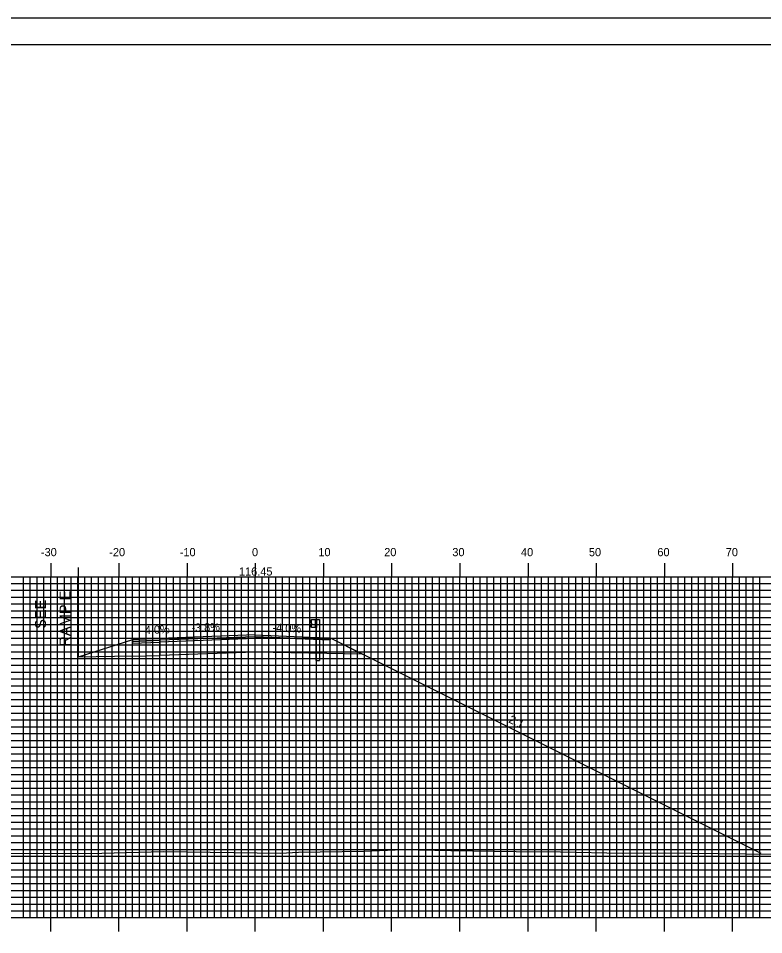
# Model space of a CAD drawing. Extents: x -302 to 42, y -1658 to -1438.
# Drawn here: x -170.6 to -61.3, y -1572.1 to -1437.7 of the extents above; entities that cross this region are included whole.
import ezdxf

# ---------------------------------------------------------------- set-up
doc = ezdxf.new("R2010")
doc.units = 0
for name, color, linetype in [('ANNOTATION', 7, 'Continuous'), ('BORDER', 7, 'Continuous'), ('D_Guardrail_Beam_Rt', 7, 'Continuous'), ('D_Roadway_Centerline_Text', 7, 'Continuous'), ('D_Roadway_Edge_Shoulder', 7, 'Continuous'), ('D_Roadway_Pavement', 7, 'Continuous'), ('D_Roadway_SlopeLines', 7, 'Continuous'), ('D_Roadway_SubGrade', 7, 'Continuous'), ('H_V ANNOTATION', 7, 'Continuous'), ('MAJOR', 7, 'Continuous'), ('MINOR', 7, 'Continuous'), ('PLOT BOUNDARY', 7, 'Continuous'), ('S_Roadway_Centerline', 7, 'Continuous')]:
    doc.layers.add(name, color=color, linetype=linetype)

msp = doc.modelspace()

# ---------------------------------------------------------------- linework, layer by layer
at = {"layer": 'BORDER'}
msp.add_lwpolyline([(-285.49, -1651.6), (34.51, -1651.6), (34.51, -1441.6), (-285.49, -1441.6)], close=True, dxfattribs=at)
at = {"layer": 'D_Guardrail_Beam_Rt'}
for p, q in [((-127.71, -1525.99), (-127.85, -1526.09)), ((-127.85, -1526.24), (-127.66, -1526.37)), ((-127.62, -1525.97), (-127.7, -1525.99)), ((-127.63, -1526.44), (-127.63, -1526.51)), ((-127.62, -1525.89), (-126.93, -1525.89)), ((-127.62, -1527.06), (-127.62, -1525.89)), ((-127.1, -1525.89), (-127.1, -1527.06)), ((-127, -1525.89), (-127, -1527.06)), ((-126.93, -1525.89), (-126.46, -1525.89)), ((-126.93, -1525.89), (-126.93, -1527.06)), ((-126.46, -1525.89), (-126.46, -1531.89)), ((-127.66, -1526.57), (-127.85, -1526.71)), ((-127.85, -1526.85), (-127.71, -1526.95)), ((-127.7, -1526.96), (-127.62, -1526.97)), ((-126.93, -1527.06), (-127.62, -1527.06)), ((-126.95, -1531.89), (-126.95, -1527.06)), ((-126.95, -1531.89), (-126.46, -1531.89))]:
    msp.add_line(p, q, dxfattribs=at)
for centre, major_axis, start_param, end_param in [((-127.8, -1526.17), (-0.0877, 0), 5.323254, 7.243116), ((-127.69, -1526.03), (-0.0417, 0), 4.907132, 5.323254), ((-127.7, -1526.44), (0.0789, 0), 0, 0.959931), ((-127.8, -1526.78), (-0.0877, 0), 5.323254, 7.243116), ((-127.69, -1526.92), (-0.0417, 0), 0.959931, 1.376053), ((-127.7, -1526.51), (0.0789, 0), 5.323254, 6.283185)]:
    msp.add_ellipse(centre, major_axis=major_axis, ratio=0.995501, start_param=start_param, end_param=end_param, dxfattribs=at)
at = {"layer": 'D_Roadway_Edge_Shoulder'}
for points in [[(-149.89, -1528.68), (-153.89, -1528.84), (-153.89, -1529.09), (-149.89, -1528.93)], [(-135.89, -1528.15), (-127.89, -1528.47), (-127.89, -1528.47), (-124.89, -1528.59), (-124.89, -1528.84), (-135.89, -1528.4)]]:
    msp.add_lwpolyline(points, close=True, dxfattribs=at)
at = {"layer": 'D_Roadway_Pavement'}
msp.add_lwpolyline([(-149.89, -1528.93), (-153.89, -1529.09), (-153.89, -1529.34), (-149.89, -1529.18)], close=True, dxfattribs=at)
msp.add_lwpolyline([(-135.89, -1528.4), (-135.89, -1528.65)], dxfattribs=at)
msp.add_lwpolyline([(-135.89, -1528.4), (-135.89, -1528.65)], dxfattribs=at)
at = {"layer": 'D_Roadway_SlopeLines'}
for p, q in [((-153.89, -1528.84), (-161.84, -1531.41)), ((-135.89, -1528.15), (-149.89, -1528.68)), ((-135.89, -1528.4), (-149.89, -1528.93)), ((-135.89, -1528.65), (-149.89, -1529.18)), ((-149.89, -1528.68), (-149.89, -1531.18)), ((-124.89, -1528.59), (-61.77, -1560.15)), ((-153.89, -1531.26), (-161.87, -1531.42)), ((-135.89, -1530.65), (-149.89, -1531.18))]:
    msp.add_line(p, q, dxfattribs=at)
at = {"layer": 'D_Roadway_SubGrade'}
for p, q in [((-161.84, -1518.27), (-161.84, -1531.41)), ((-153.89, -1531.26), (-149.89, -1531.18))]:
    msp.add_line(p, q, dxfattribs=at)
msp.add_lwpolyline([(-135.89, -1528.65), (-135.89, -1528.4), (-124.89, -1528.84), (-124.89, -1528.59), (-120.14, -1530.97), (-135.89, -1530.65)], close=True, dxfattribs=at)
at = {"layer": 'MAJOR'}
for p, q in [((-165.89, -1517.6), (-165.89, -1519.6)), ((-155.89, -1517.6), (-155.89, -1519.6)), ((-145.89, -1517.6), (-145.89, -1519.6)), ((-135.89, -1517.6), (-135.89, -1519.6)), ((-125.89, -1517.6), (-125.89, -1519.6)), ((-115.89, -1517.6), (-115.89, -1519.6)), ((-105.89, -1517.6), (-105.89, -1519.6)), ((-95.89, -1517.6), (-95.89, -1519.6)), ((-85.89, -1517.6), (-85.89, -1519.6)), ((-75.89, -1517.6), (-75.89, -1519.6)), ((-65.89, -1517.6), (-65.89, -1519.6)), ((-275.89, -1519.6), (4.11, -1519.6)), ((-275.89, -1519.6), (4.11, -1519.6)), ((-165.89, -1569.6), (-165.89, -1519.6)), ((-155.89, -1569.6), (-155.89, -1519.6)), ((-145.89, -1569.6), (-145.89, -1519.6)), ((-135.89, -1569.6), (-135.89, -1519.6)), ((-125.89, -1569.6), (-125.89, -1519.6)), ((-115.89, -1569.6), (-115.89, -1519.6)), ((-105.89, -1569.6), (-105.89, -1519.6)), ((-95.89, -1569.6), (-95.89, -1519.6)), ((-85.89, -1569.6), (-85.89, -1519.6)), ((-75.89, -1569.6), (-75.89, -1519.6)), ((-65.89, -1569.6), (-65.89, -1519.6)), ((-275.89, -1524.6), (4.11, -1524.6)), ((-275.89, -1529.6), (4.11, -1529.6)), ((-275.89, -1534.6), (4.11, -1534.6)), ((-275.89, -1539.6), (4.11, -1539.6)), ((-275.89, -1544.6), (4.11, -1544.6)), ((-275.89, -1549.6), (4.11, -1549.6)), ((-275.89, -1554.6), (4.11, -1554.6)), ((-275.89, -1559.6), (4.11, -1559.6)), ((-275.89, -1564.6), (4.11, -1564.6)), ((-275.89, -1569.6), (4.11, -1569.6)), ((-275.89, -1569.6), (4.11, -1569.6)), ((-165.89, -1571.61), (-165.89, -1569.6)), ((-155.89, -1571.61), (-155.89, -1569.6)), ((-145.89, -1571.61), (-145.89, -1569.6)), ((-135.89, -1571.61), (-135.89, -1569.6)), ((-125.89, -1571.61), (-125.89, -1569.6)), ((-115.89, -1571.61), (-115.89, -1569.6)), ((-105.89, -1571.61), (-105.89, -1569.6)), ((-95.89, -1571.61), (-95.89, -1569.6)), ((-85.89, -1571.61), (-85.89, -1569.6)), ((-75.89, -1571.61), (-75.89, -1569.6)), ((-65.89, -1571.61), (-65.89, -1569.6))]:
    msp.add_line(p, q, dxfattribs=at)
at = {"layer": 'MINOR'}
for p, q in [((-169.89, -1569.6), (-169.89, -1519.6)), ((-168.89, -1569.6), (-168.89, -1519.6)), ((-167.89, -1569.6), (-167.89, -1519.6)), ((-166.89, -1569.6), (-166.89, -1519.6)), ((-164.89, -1569.6), (-164.89, -1519.6)), ((-163.89, -1569.6), (-163.89, -1519.6)), ((-162.89, -1569.6), (-162.89, -1519.6)), ((-161.89, -1569.6), (-161.89, -1519.6)), ((-160.89, -1569.6), (-160.89, -1519.6)), ((-159.89, -1569.6), (-159.89, -1519.6)), ((-158.89, -1569.6), (-158.89, -1519.6)), ((-157.89, -1569.6), (-157.89, -1519.6)), ((-156.89, -1569.6), (-156.89, -1519.6)), ((-154.89, -1569.6), (-154.89, -1519.6)), ((-153.89, -1569.6), (-153.89, -1519.6)), ((-152.89, -1569.6), (-152.89, -1519.6)), ((-151.89, -1569.6), (-151.89, -1519.6)), ((-150.89, -1569.6), (-150.89, -1519.6)), ((-149.89, -1569.6), (-149.89, -1519.6)), ((-148.89, -1569.6), (-148.89, -1519.6)), ((-147.89, -1569.6), (-147.89, -1519.6)), ((-146.89, -1569.6), (-146.89, -1519.6)), ((-144.89, -1569.6), (-144.89, -1519.6)), ((-143.89, -1569.6), (-143.89, -1519.6)), ((-142.89, -1569.6), (-142.89, -1519.6)), ((-141.89, -1569.6), (-141.89, -1519.6)), ((-140.89, -1569.6), (-140.89, -1519.6)), ((-139.89, -1569.6), (-139.89, -1519.6)), ((-138.89, -1569.6), (-138.89, -1519.6)), ((-137.89, -1569.6), (-137.89, -1519.6)), ((-136.89, -1569.6), (-136.89, -1519.6)), ((-134.89, -1569.6), (-134.89, -1519.6)), ((-133.89, -1569.6), (-133.89, -1519.6)), ((-132.89, -1569.6), (-132.89, -1519.6)), ((-131.89, -1569.6), (-131.89, -1519.6)), ((-130.89, -1569.6), (-130.89, -1519.6)), ((-129.89, -1569.6), (-129.89, -1519.6)), ((-128.89, -1569.6), (-128.89, -1519.6)), ((-127.89, -1569.6), (-127.89, -1519.6)), ((-126.89, -1569.6), (-126.89, -1519.6)), ((-124.89, -1569.6), (-124.89, -1519.6)), ((-123.89, -1569.6), (-123.89, -1519.6)), ((-122.89, -1569.6), (-122.89, -1519.6)), ((-121.89, -1569.6), (-121.89, -1519.6)), ((-120.89, -1569.6), (-120.89, -1519.6)), ((-119.89, -1569.6), (-119.89, -1519.6)), ((-118.89, -1569.6), (-118.89, -1519.6)), ((-117.89, -1569.6), (-117.89, -1519.6)), ((-116.89, -1569.6), (-116.89, -1519.6)), ((-114.89, -1569.6), (-114.89, -1519.6)), ((-113.89, -1569.6), (-113.89, -1519.6)), ((-112.89, -1569.6), (-112.89, -1519.6)), ((-111.89, -1569.6), (-111.89, -1519.6)), ((-110.89, -1569.6), (-110.89, -1519.6)), ((-109.89, -1569.6), (-109.89, -1519.6)), ((-108.89, -1569.6), (-108.89, -1519.6)), ((-107.89, -1569.6), (-107.89, -1519.6)), ((-106.89, -1569.6), (-106.89, -1519.6)), ((-104.89, -1569.6), (-104.89, -1519.6)), ((-103.89, -1569.6), (-103.89, -1519.6)), ((-102.89, -1569.6), (-102.89, -1519.6)), ((-101.89, -1569.6), (-101.89, -1519.6)), ((-100.89, -1569.6), (-100.89, -1519.6)), ((-99.89, -1569.6), (-99.89, -1519.6)), ((-98.89, -1569.6), (-98.89, -1519.6)), ((-97.89, -1569.6), (-97.89, -1519.6)), ((-96.89, -1569.6), (-96.89, -1519.6)), ((-94.89, -1569.6), (-94.89, -1519.6)), ((-93.89, -1569.6), (-93.89, -1519.6)), ((-92.89, -1569.6), (-92.89, -1519.6)), ((-91.89, -1569.6), (-91.89, -1519.6)), ((-90.89, -1569.6), (-90.89, -1519.6)), ((-89.89, -1569.6), (-89.89, -1519.6)), ((-88.89, -1569.6), (-88.89, -1519.6)), ((-87.89, -1569.6), (-87.89, -1519.6)), ((-86.89, -1569.6), (-86.89, -1519.6)), ((-84.89, -1569.6), (-84.89, -1519.6)), ((-83.89, -1569.6), (-83.89, -1519.6)), ((-82.89, -1569.6), (-82.89, -1519.6)), ((-81.89, -1569.6), (-81.89, -1519.6)), ((-80.89, -1569.6), (-80.89, -1519.6)), ((-79.89, -1569.6), (-79.89, -1519.6)), ((-78.89, -1569.6), (-78.89, -1519.6)), ((-77.89, -1569.6), (-77.89, -1519.6)), ((-76.89, -1569.6), (-76.89, -1519.6)), ((-74.89, -1569.6), (-74.89, -1519.6)), ((-73.89, -1569.6), (-73.89, -1519.6)), ((-72.89, -1569.6), (-72.89, -1519.6)), ((-71.89, -1569.6), (-71.89, -1519.6)), ((-70.89, -1569.6), (-70.89, -1519.6)), ((-69.89, -1569.6), (-69.89, -1519.6)), ((-68.89, -1569.6), (-68.89, -1519.6)), ((-67.89, -1569.6), (-67.89, -1519.6)), ((-66.89, -1569.6), (-66.89, -1519.6)), ((-64.89, -1569.6), (-64.89, -1519.6)), ((-63.89, -1569.6), (-63.89, -1519.6)), ((-62.89, -1569.6), (-62.89, -1519.6)), ((-61.89, -1569.6), (-61.89, -1519.6)), ((-275.89, -1520.6), (4.11, -1520.6)), ((-275.89, -1521.6), (4.11, -1521.6)), ((-275.89, -1522.6), (4.11, -1522.6)), ((-275.89, -1523.6), (4.11, -1523.6)), ((-275.89, -1525.6), (4.11, -1525.6)), ((-275.89, -1526.6), (4.11, -1526.6)), ((-275.89, -1527.6), (4.11, -1527.6)), ((-275.89, -1528.6), (4.11, -1528.6)), ((-275.89, -1530.6), (4.11, -1530.6)), ((-275.89, -1531.6), (4.11, -1531.6)), ((-275.89, -1532.6), (4.11, -1532.6)), ((-275.89, -1533.6), (4.11, -1533.6)), ((-275.89, -1535.6), (4.11, -1535.6)), ((-275.89, -1536.6), (4.11, -1536.6)), ((-275.89, -1537.6), (4.11, -1537.6)), ((-275.89, -1538.6), (4.11, -1538.6)), ((-275.89, -1540.6), (4.11, -1540.6)), ((-275.89, -1541.6), (4.11, -1541.6)), ((-275.89, -1542.6), (4.11, -1542.6)), ((-275.89, -1543.6), (4.11, -1543.6)), ((-275.89, -1545.6), (4.11, -1545.6)), ((-275.89, -1546.6), (4.11, -1546.6)), ((-275.89, -1547.6), (4.11, -1547.6)), ((-275.89, -1548.6), (4.11, -1548.6)), ((-275.89, -1550.6), (4.11, -1550.6)), ((-275.89, -1551.6), (4.11, -1551.6)), ((-275.89, -1552.6), (4.11, -1552.6)), ((-275.89, -1553.6), (4.11, -1553.6)), ((-275.89, -1555.6), (4.11, -1555.6)), ((-275.89, -1556.6), (4.11, -1556.6)), ((-275.89, -1557.6), (4.11, -1557.6)), ((-275.89, -1558.6), (4.11, -1558.6)), ((-275.89, -1560.6), (4.11, -1560.6)), ((-275.89, -1561.6), (4.11, -1561.6)), ((-275.89, -1562.6), (4.11, -1562.6)), ((-275.89, -1563.6), (4.11, -1563.6)), ((-275.89, -1565.6), (4.11, -1565.6)), ((-275.89, -1566.6), (4.11, -1566.6)), ((-275.89, -1567.6), (4.11, -1567.6)), ((-275.89, -1568.6), (4.11, -1568.6))]:
    msp.add_line(p, q, dxfattribs=at)
at = {"layer": 'PLOT BOUNDARY'}
msp.add_lwpolyline([(-301.68, -1657.72), (38.32, -1657.72), (38.32, -1437.72), (-301.68, -1437.72)], close=True, dxfattribs=at)
at = {"layer": 'S_Roadway_Centerline'}
msp.add_lwpolyline([(-182.37, -1560.12), (-163.66, -1560.2), (-158.39, -1560.13), (-149.33, -1559.9), (-132.18, -1560.13), (-129.56, -1560), (-119.95, -1559.84), (-114.22, -1559.62), (-107.19, -1559.75), (-97.62, -1559.88), (-91.11, -1559.95), (-82.07, -1560.13), (-75.71, -1560.09), (-56.16, -1560.33), (-54.35, -1560.37), (-37.14, -1560.02), (-32.89, -1559.92), (-32.43, -1559.93), (-12.66, -1559.66), (-7.94, -1559.7), (2.5, -1560.13), (4.11, -1560.13)], dxfattribs=at)

# ---------------------------------------------------------------- texts
at = {"layer": 'ANNOTATION'}
for s, height, rotation, p in [('RAMP E', 1.6, 90, (-162.99, -1529.86)), ('SEE', 1.6, 90, (-166.59, -1527.25)), ('-3.8%', 1.2, 1.7731, (-145.24, -1527.69)), ('-4.0%', 1.2, 357.7094, (-133.38, -1527.64)), ('-4.0%', 1.2, 2.2236, (-152.6, -1528.05)), ('2:1', 1.2, 333.4349, (-98.84, -1540.92))]:
    msp.add_text(s, height=height, rotation=rotation, dxfattribs=at).set_placement(p)
at = {"layer": 'D_Roadway_Centerline_Text'}
msp.add_text('116.45', height=1.2, dxfattribs=at).set_placement((-138.28, -1519.44))
at = {"layer": 'H_V ANNOTATION'}
for s, p in [('-30', (-167.32, -1516.6)), ('-20', (-157.3, -1516.6)), ('-10', (-146.96, -1516.6)), ('0', (-136.37, -1516.6)), ('10', (-126.64, -1516.6)), ('20', (-116.98, -1516.6)), ('30', (-106.99, -1516.6)), ('40', (-96.92, -1516.6)), ('50', (-86.96, -1516.6)), ('60', (-76.92, -1516.6)), ('70', (-66.89, -1516.6))]:
    msp.add_text(s, height=1.2, dxfattribs=at).set_placement(p)

doc.saveas('drawing.dxf')
